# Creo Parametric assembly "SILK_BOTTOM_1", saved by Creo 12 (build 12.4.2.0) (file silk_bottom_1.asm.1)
Units: Custom; MM, KILOGRAM, SECS

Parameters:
  PTC_WM_ITERATION = "0"
  PTC_WM_VERSION = "-.0"
  PTC_WM_LIFECYCLE_STATE = "In Work"
  PTC_WM_LIFECYCLE = "MO_CADDocument"
  PTC_WM_CREATED_BY = "Maximilian Roepper (Z0017RMS: MO)"
  PTC_WM_CREATED_ON = "18-Sep-26 11:36:42 AM"
  PTC_WM_MODIFIED_BY = "Maximilian Roepper (Z0017RMS: MO)"
  PTC_WM_MODIFIED_ON = "18-Sep-26 11:36:46 AM"
  PDMLINKNUMBER = "PDM000071455008"
  PTC_WM_NUMBER = "PDM000071455008"

Other parameters: WEIGHT, WEIGHT_FACTOR, WEIGHT_ADD, MC_ERRORS, SUPPLIER

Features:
  1. coordinate system
  2. imported feature
  3. component "RES_SILK_1"
  4. component "RES_SILK001_1"
  5. component "RES_SILK002_1"
  6. component "RES_SILK003_1"
  7. component "RES_SILK004_1"
  8. component "RES_SILK005_1"
  9. component "CAP_SILK001_1"
  10. component "CAP_SILK002_1"
  11. component "SOT23_001_1"
  12. component "SOT23_002_1"
  13. component "U2_SILK002_1"
  14. component "SD_SILK001_1"
  15. component "TOUCH_1"
  16. component "TEXT_1"
  17. component "J_SILK006_1"

Other named items: DRW_VIEW_ORG, ROUGH-GROB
